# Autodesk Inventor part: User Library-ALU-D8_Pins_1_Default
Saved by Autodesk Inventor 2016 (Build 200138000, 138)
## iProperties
Created: 2012-01
Part Number: User Library-ALU-D8_Pins_1_Default
Document SubType Name: Modeling
Designer: Trevor
Density: 1 g/cm^3
Material: Generic
Appearance: 202,202,202
Author: Trevor
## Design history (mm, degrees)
feature "Base1"
node "Imported1"
